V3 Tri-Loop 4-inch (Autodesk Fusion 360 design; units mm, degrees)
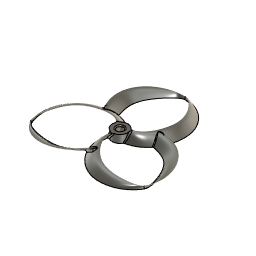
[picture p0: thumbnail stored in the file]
sketch "Hub 5mm Shaft" plane through (0, 0, 0) normal (0, 0, 1) x axis (1, 0, 0)
  circle C1 centre (0, 0) radius 2.6
  circle C2 centre (0, 0) radius 6
  point P1 (0, 0)
  point P2 (0, 0)
  coincident P1 P2
  concentric C1 C2
  dimension "d28" diameter C1 = 5.2
  dimension "d29" diameter C2 = 12
  dimension "d161" Radius = 1
  dimension "d172" Radius = 1
extrude "Extrude2" new body sketch "Hub 5mm Shaft" along normal blind 6 bodies "Hub 5mm Shaft"
work_plane "WorkPlane9" AlongDistance 2.5
work_plane "WorkPlane10" AlongDistance -2.5
sketch "Profile Start" plane through (2.5, 0, 0) normal (1, 0, 0) x axis (0, 1, 0)
  line L1 (-2.1, 0) -> (-3, 0)
  curve K1 (-3, 0) -> (-2.1, 0)
  curve K2 (-4, -1.5) -> (-2, 1.5)
  curve K3 (-1, 1.5) -> (-3.2, -1.5)
  curve K4 (2.75, 6) -> (3.25, 6)
  point P2 (-3, 0)
  point P4 (-2.1, 0)
  point P3 (3, 6)
  point P1 (0, 0)
  point P5 (-2, 1.5)
  point P8 (-1, 1.5)
  point P9 (3.25, 6)
  point P10 (2.75, 6)
  horizontal L1
  midpoint P2 K2
  midpoint P4 K3
  midpoint P3 K4
  dimension "d65" distance P1 P3 = 3
  dimension "d66" distance P1 P3 = 6
  dimension "d67" distance P1 P2 = 3
  dimension "d68" distance P2 P5 = 1
  dimension "d69" distance P2 P5 = 1.5
  dimension "d70" distance P4 P8 = 1.5
  dimension "d71" distance P5 P8 = 1
  dimension "d72" distance P9 P10 = 0.5
  dimension "d134" distance P2 P4 = 0.9
sketch "Profile End" plane through (-2.5, 0, 0) normal (1, 0, 0) x axis (0, 1, 0)
  curve K1 (3, 0) -> (2.2, 0)
  curve K2 (1.5, 1.5) -> (3.3196, -1.2262)
  curve K3 (-1.75, 5) -> (-2.25, 5)
  curve K4 (4, -1.5) -> (2, 1.5)
  line L1 (-1.75, 5) -> (-2.25, 5)
  line L2 (2.2, 0) -> (3, 0)
  point P5 (-1.75, 5)
  point P9 (-2.25, 5)
  point P4 (2.2, 0)
  point P8 (3, 0)
  point P6 (-2, 5)
  point P11 (0, 0)
  point P3 (1.5, 1.5)
  point P7 (2, 1.5)
  dimension "d84" distance P5 P9 = 0.5
  dimension "d89" distance P4 P8 = 0.8
  dimension "d101" distance P6 P11 = 5
  dimension "d102" distance P6 P11 = 2
  dimension "d103" distance P8 P11 = 3
  dimension "d104" distance P3 P11 = 1.5
  dimension "d105" distance P3 P11 = 1.5
  dimension "d106" distance P7 P11 = 2
  dimension "d107" distance P7 P11 = 1.5
sketch "Target Shape" plane through (0, 0, 0) normal (0, 0, 1) x axis (1, 0, 0)
  line L1 (0, 50.8) -> (0, 0)
  line L2 (25.4, 25.4) -> (0, 25.4)
  line L3 (-25.4, 25.4) -> (0, 25.4)
  circle C1 centre (0, 0) radius 50.8
  circle C2 centre (0, 25.4) radius 25.4
  point P1 (0, 0)
  point P2 (0, 0)
  point P7 (0, 0)
  point P8 (0, 50.8)
  point P9 (0, 25.4)
  point P10 (0, 25.4)
  point P11 (25.4, 25.4)
  point P12 (0, 25.4)
  point P13 (-25.4, 25.4)
  coincident P1 P2
  coincident P2 P7
  coincident C1 P8
  midpoint L1 P9
  coincident P8 C2
  coincident P9 P10
  coincident C2 P11
  perpendicular L1 L2
  coincident P9 P12
  coincident C2 P13
  perpendicular L1 L3
  dimension "d95" diameter C1 = 101.6
sketch "Profile Edge" plane through (0, 0, 0) normal (1, 0, 0) x axis (0, 1, 0)
  line L1 (50.8, 0) -> (50.3, 0)
  curve K1 (50.3, 0) -> (50.8, 0)
  curve K2 (50.45, 2) -> (50.65, 2)
  curve K3 (50.8, 0.8) -> (50.8, -0.8)
  curve K4 (50.3, -0.8) -> (50.3, 0.8)
  point P4 (50.55, 2)
  point P3 (50.8, 0)
  point P2 (50.3, 0)
  point P1 (0, 0)
  point P5 (50.65, 2)
  point P6 (50.45, 2)
  horizontal L1
  midpoint P4 K2
  midpoint P3 K3
  midpoint P2 K4
  dimension "d96" distance P2 P3 = 0.5
  dimension "d98" distance P3 P4 = 2
  dimension "d121" distance P1 P4 = 2
  dimension "d138" distance P5 P6 = 0.2
  dimension "d177" distance P1 P3 = 50.8
work_plane "WorkPlane11" AlongDistance 25.4 (= "( 101.6 / 4 ) * 1 mm")
sketch "Profile Mid" plane through (0, 25.4, 0) normal (0, 1, 0) x axis (1, 0, 0)
  line L1 (24.6, 0) -> (25.4, 0)
  curve K1 (24.6, 0) -> (25.4, 0)
  curve K2 (17.15, -5) -> (17.65, -5)
  curve K3 (26.6, 1.5) -> (22.6, -1.5)
  curve K4 (23.7593, -1.5) -> (27.0407, 1.5)
  line L2 (-18.2, 0) -> (-17.4, 0)
  curve K5 (-18.2, 0) -> (-17.4, 0)
  curve K6 (-19.2593, -1.5) -> (-15.5407, 1.5)
  curve K7 (-25.6, -5) -> (-25.2, -5)
  curve K8 (-16.2, 1.5) -> (-20.2, -1.5)
  point P3 (17.4, -5)
  point P4 (24.6, 0)
  point P2 (25.4, 0)
  point P15 (-25.4, -5)
  point P14 (-18.2, 0)
  point P11 (-17.4, 0)
  point P5 (17.65, -5)
  point P6 (17.15, -5)
  point P1 (0, 0)
  point P18 (-25.6, -5)
  point P19 (-25.2, -5)
  midpoint P3 K2
  midpoint P4 K3
  midpoint P2 K4
  midpoint P15 K7
  midpoint P14 K8
  midpoint P11 K6
  dimension "d109" distance P2 P4 = 0.8
  dimension "d110" distance P2 P3 = 5
  dimension "d111" distance P2 P3 = 8
  dimension "d112" distance P5 P6 = 0.5
  dimension "d113" distance P1 P2 = 25.4
  dimension "d114" distance P11 P14 = 0.8
  dimension "d115" distance P11 P15 = 5
  dimension "d116" distance P11 P15 = 8
  dimension "d117" distance P18 P19 = 0.4
  dimension "d118" distance P1 P15 = 25.4
sketch "Lower Rails" plane through (0, 0, 0) normal (0, 0, 1) x axis (1, 0, 0)
  curve K1 (-2.5, 2.2) -> (0.0002, 50.8006)
  curve K2 (2, 1.7) -> (-7, 2.7)
  curve K3 (-18.2093, 21.275) -> (-18.1907, 29.525)
  curve K4 (-1.4998, 50.7997) -> (1.5002, 50.8015)
  curve K5 (-2.5, 3) -> (0, 50.3)
  curve K6 (2, 2.5) -> (-7, 3.5)
  curve K7 (-17.3941, 21.7775) -> (-17.4059, 29.0225)
  curve K8 (-1.5, 50.3) -> (1.5, 50.3)
  curve K9 (0, 50.8005) -> (2.5, -3)
  curve K10 (-6, 50.8005) -> (6, 50.8005)
  curve K11 (25.2, 31.4) -> (25.6, 19.4)
  curve K12 (9.7325, -2.2212) -> (-4.7325, -3.7788)
  arc A1 centre (-1.7632, 23.9562) radius 26.4027 clockwise from (0, 50.3) to (2.5, -2.1)
  point P8 (24.6, 25.4)
  point P9 (-18.2, 25.4)
  point P11 (-18.2, 25.4)
  point P10 (-2.5, 2.2)
  point P12 (-2.5, 2.2)
  point P32 (0.0002, 50.8006)
  point P5 (0, 50.3)
  point P19 (0, 50.3)
  point P20 (-17.4, 25.4)
  point P22 (-17.4, 25.4)
  point P4 (-2.5, 3)
  point P21 (-2.5, 3)
  point P31 (2.5, -3)
  point P33 (2.5, -3)
  point P30 (25.4, 25.4)
  point P34 (25.4, 25.4)
  point P35 (0, 50.8005)
  point P27 (1.5, 50.3)
  point P28 (-1.5, 50.3)
  point P17 (1.5002, 50.8015)
  point P18 (-1.4998, 50.7997)
  coincident P8 A1
  coincident P9 P11
  coincident P10 P12
  midpoint P12 K2
  midpoint P11 K3
  midpoint K4 P32
  coincident P5 P19
  coincident P20 P22
  coincident P4 P21
  midpoint P21 K6
  parallel K2 K6
  midpoint P20 K7
  midpoint P19 K8
  coincident P31 P33
  coincident P30 P34
  midpoint P35 K10
  midpoint P34 K11
  midpoint P33 K12
  dimension "d136" distance P27 P28 = 3
  dimension "d137" distance P17 P18 = 3
work_plane "WorkPlane12" AlongDistance 6
sketch "Upper Rails" plane through (0, 0, 6) normal (0, 0, 1) x axis (1, 0, 0)
  line L1 (0, 50.8) -> (0, 50.3)
  curve K1 (2.5, 3) -> (0, 50.55)
  curve K2 (-1.2, 3) -> (6.2, 3)
  curve K3 (17.4094, 21.2744) -> (17.3908, 29.5244)
  curve K4 (1.5, 50.55) -> (-1.5, 50.55)
  curve K5 (-2.5, -2) -> (0, 50.55)
  curve K6 (2, -2) -> (-7, -2)
  curve K7 (-5, 50.55) -> (5, 50.55)
  curve K8 (-25.5406, 20.5252) -> (-25.2592, 30.2752)
  point P7 (2.5, 3)
  point P9 (2.5, 3)
  point P6 (17.4001, 25.3994)
  point P5 (0, 50.55)
  point P16 (0, 50.55)
  point P18 (-2.5, -2)
  point P17 (-25.3999, 25.4002)
  point P14 (-1.5, 50.55)
  point P15 (1.5, 50.55)
  coincident P7 P9
  midpoint P7 K2
  midpoint P6 K3
  midpoint P5 K4
  coincident P5 P16
  midpoint P18 K6
  midpoint P16 K7
  midpoint P17 K8
  dimension "d135" distance P14 P15 = 3
loft "Loft3" sketch "Profile Start" + "Profile Mid" + "Profile Edge" bodies "Blade Template 4x3x3"
loft "Loft4" sketch "Profile Edge" + "Profile Mid" + "Profile End"
circular_pattern "C-Pattern2" TotalAngle 360
combine "Combine2" bodies "Blade Template 4x3x3 (1)"
offset_faces "OffsetFaces5" distance -0.5
circular_pattern "C-Pattern3" TotalAngle 360
combine "Combine3"
fillet "Fillet7" radius 1
circular_pattern "C-Pattern4" TotalAngle 360 bodies "Blade Template 4x3x3 (2)", "Blade Template 4x3x3 (3)"
combine "Combine8" bodies "Blade Template 4x3x3 (2)", "Blade Template 4x3x3 (3)"
chamfer "Chamfer1" distance 0.75
copy_paste_bodies "CopyPasteBodies1"
offset_faces "OffsetFaces3" distance 2
combine "Combine4"
fillet "Fillet8" radius 1
offset_faces "OffsetFaces4" distance -2
mirror "Mirror1" mirrorStitchTolerance 0.1 bodies "4x3x3 CW"
sketch "Hub 5mm T-Mount" plane through (0, 0, 0) normal (0, 0, 1) x axis (1, 0, 0)
  circle C1 centre (0, 0) radius 6
  circle C2 centre (0, 0) radius 0.8
  circle C3 centre (2.5, 0) radius 1.05
  circle C4 centre (-2.5, 0) radius 1.05
  point P1 (0, 0)
  point P2 (0, 0)
  point P3 (0, 0)
  point P5 (-2.5, 0)
  point P4 (2.5, 0)
  coincident P1 P2
  concentric C1 C2
  dimension "d150" diameter C1 = 12
  dimension "d151" diameter C2 = 1.6
  dimension "d152" diameter C3 = 2.1
  dimension "d153" diameter C4 = 2.1
  dimension "d154" distance P3 P5 = 2.5
  dimension "d155" distance P3 P4 = 2.5
extrude "Extrude4" new body sketch "Hub 5mm T-Mount" along normal blind 6 bodies "Hub 5mm T-Mount"
chamfer "Chamfer2" distance 0.25
copy_paste_bodies "CopyPasteBodies4"
offset_faces "OffsetFaces8" distance 2
combine "Combine9"
fillet "Fillet9" radius 1
chamfer "Chamfer6" distance 0.25
offset_faces "OffsetFaces12" distance -2
mirror "Mirror5" mirrorStitchTolerance 0.1 bodies "4x3x3T CW"
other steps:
combine "OffsetFaces10" distance -1
combine "OffsetFaces9" distance -2
step "Chamfer4" Distance 0.25
step "Mirror3" mirrorStitchTolerance 0.1
combine "OffsetFaces11" distance -2
step "Chamfer5" Distance 0.25
step "Mirror4" mirrorStitchTolerance 0.1
base_feature "Base Feature1" bodies "Hub 5mm Shaft", "4x3x3 CCW"
base_feature "Base Feature4" bodies "Hub 5mm T-Mount", "4x3x3T CCW"
named bodies: "Hub 5mm Shaft", "Blade Template 4x3x3", "4x3x3 CCW", "4x3x3 CW", "Hub 5mm T-Mount", "4x3x3T CCW", "Blade Template 4x3x3 (1)", "Blade Template 4x3x3 (2)", "Blade Template 4x3x3 (3)", "4x3x3T CW"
